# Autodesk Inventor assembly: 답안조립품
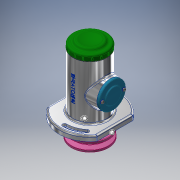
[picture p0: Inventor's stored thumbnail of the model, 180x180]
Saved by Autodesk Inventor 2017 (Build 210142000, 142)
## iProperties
Part Number: 답안조립품
Material: 일반
Document SubType Name: Assembly
Designer: MRC
Author: MRC
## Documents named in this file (22)
- C:\Users\MRC\Documents\Inventor\720506V1014\답안조립품.iam
- C:\Users\MRC\Documents\Inventor\720506V1014\본체.ipt
- C:\Users\MRC\Documents\Inventor\720506V1014\720506V1014\V-벨트풀리.ipt
- C:\Users\MRC\Documents\Inventor\720506V1014\720506V1014\개스킷.ipt
- C:\Users\MRC\Documents\Inventor\720506V1014\720506V1014\너트 M10.ipt
- C:\Users\MRC\Documents\Inventor\720506V1014\720506V1014\멈춤나사 M3.ipt
- C:\Users\MRC\Documents\Inventor\720506V1014\720506V1014\멈춤링 15 x 1.ipt
- C:\Users\MRC\Documents\Inventor\720506V1014\720506V1014\멈춤링 35 x 1.6.ipt
- C:\Users\MRC\Documents\Inventor\720506V1014\720506V1014\베어링 6202.ipt
- C:\Users\MRC\Documents\Inventor\720506V1014\720506V1014\볼트 M4 x 10.ipt
- C:\Users\MRC\Documents\Inventor\720506V1014\720506V1014\부시1.ipt
- C:\Users\MRC\Documents\Inventor\720506V1014\720506V1014\부시2.ipt
- C:\Users\MRC\Documents\Inventor\720506V1014\720506V1014\사이드 커버.ipt
- 사이드 커버.ipt
- C:\Users\MRC\Documents\Inventor\720506V1014\720506V1014\십자볼트 M3 x 10.ipt
- C:\Users\MRC\Documents\Inventor\720506V1014\720506V1014\오일 실 15 x 30 x 7.ipt
- C:\Users\MRC\Documents\Inventor\720506V1014\720506V1014\와셔 3 x 6.ipt
- C:\Users\MRC\Documents\Inventor\720506V1014\720506V1014\와셔 4 x 16.ipt
- C:\Users\MRC\Documents\Inventor\720506V1014\720506V1014\와셔 10 x 21.ipt
- C:\Users\MRC\Documents\Inventor\720506V1014\720506V1014\축.ipt
- C:\Users\MRC\Documents\Inventor\720506V1014\720506V1014\키 4 x 4.ipt
- C:\Users\MRC\Documents\Inventor\720506V1014\720506V1014\탑 커버.ipt
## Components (3 placed, 3 different names)
1. V-벨트풀리:1 — 플러쉬:1
2. 개스킷:1
3. ISO 4017 M4 x 10:1 — 각도:1
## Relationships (2: Flush 1, Angle 1)
- 플러쉬:1 [Flush]: V-벨트풀리:1
- 각도:1 [Angle]: ISO 4017 M4 x 10:1
